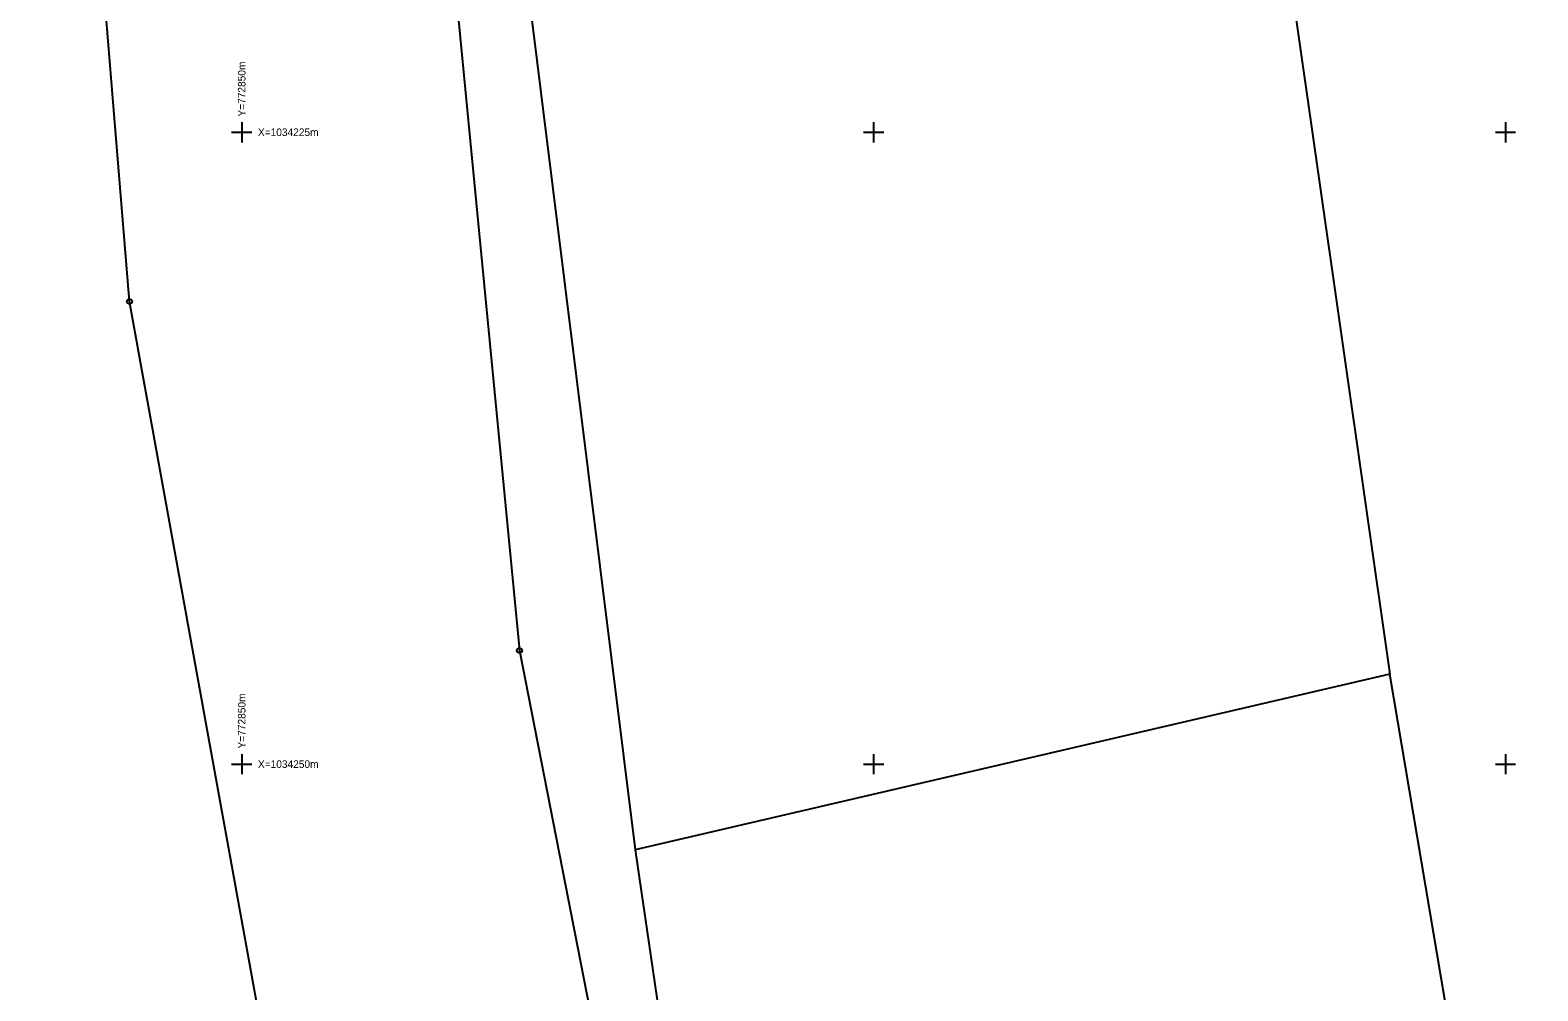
# Model space of a CAD drawing. Extents: x -772865 to -772533, y -1034366 to -1034132.
# Drawn here: x -772858.4 to -772798.7, y -1034259 to -1034221 of the extents above; entities that cross this region are included whole.
import ezdxf

# ---------------------------------------------------------------- set-up
doc = ezdxf.new("R2010")
doc.units = 0
for name, color, linetype in [('KM_hranice', 7, 'Continuous'), ('KM_mezni_znaky', 7, 'Continuous'), ('souradnicova_sit', 7, 'Continuous')]:
    doc.layers.add(name, color=color, linetype=linetype)

msp = doc.modelspace()

# ---------------------------------------------------------------- linework, layer by layer
at = {"layer": 'KM_hranice'}
for p, q in [((-772854.44, -1034231.7), (-772858.37, -1034183.47)), ((-772843.52, -1034198.83), (-772839.01, -1034245.51)), ((-772840, -1034208.77), (-772834.43, -1034253.39)), ((-772809.91, -1034209.22), (-772804.57, -1034246.44)), ((-772847.32, -1034270.94), (-772854.44, -1034231.7)), ((-772839.01, -1034245.51), (-772830.43, -1034289.37)), ((-772804.57, -1034246.44), (-772834.43, -1034253.39)), ((-772798.72, -1034281.08), (-772804.57, -1034246.44)), ((-772834.43, -1034253.39), (-772829.03, -1034290.24))]:
    msp.add_line(p, q, dxfattribs=at)
at = {"layer": 'KM_mezni_znaky'}
for p, q in [((-772854.464, -1034231.7), (-772854.416, -1034231.7)), ((-772839.034, -1034245.51), (-772838.986, -1034245.51))]:
    msp.add_line(p, q, dxfattribs=at)
for points in [[(-772854.41, -1034231.604), (-772854.36, -1034231.64), (-772854.34, -1034231.698), (-772854.36, -1034231.756), (-772854.41, -1034231.792), (-772854.472, -1034231.792), (-772854.522, -1034231.756), (-772854.542, -1034231.698), (-772854.522, -1034231.64), (-772854.472, -1034231.604)], [(-772838.98, -1034245.414), (-772838.93, -1034245.45), (-772838.91, -1034245.508), (-772838.93, -1034245.566), (-772838.98, -1034245.602), (-772839.042, -1034245.602), (-772839.092, -1034245.566), (-772839.112, -1034245.508), (-772839.092, -1034245.45), (-772839.042, -1034245.414)]]:
    msp.add_lwpolyline(points, close=True, dxfattribs=at)
at = {"layer": 'souradnicova_sit'}
for p, q in [((-772850, -1034224.6), (-772850, -1034225.4)), ((-772825, -1034224.6), (-772825, -1034225.4)), ((-772800, -1034224.6), (-772800, -1034225.4)), ((-772850.4, -1034225), (-772849.6, -1034225)), ((-772825.4, -1034225), (-772824.6, -1034225)), ((-772800.4, -1034225), (-772799.6, -1034225)), ((-772850, -1034249.6), (-772850, -1034250.4)), ((-772825, -1034249.6), (-772825, -1034250.4)), ((-772800, -1034249.6), (-772800, -1034250.4)), ((-772850.4, -1034250), (-772849.6, -1034250)), ((-772825.4, -1034250), (-772824.6, -1034250)), ((-772800.4, -1034250), (-772799.6, -1034250))]:
    msp.add_line(p, q, dxfattribs=at)

# ---------------------------------------------------------------- texts
for p in [(-772849.85, -1034224.381), (-772849.85, -1034249.381)]:
    msp.add_text('Y=772850m', height=0.3, rotation=90.01167, dxfattribs=at).set_placement(p)
for s, p in [('X=1034225m', (-772849.358, -1034225.15)), ('X=1034250m', (-772849.358, -1034250.15))]:
    msp.add_text(s, height=0.3, dxfattribs=at).set_placement(p)

doc.saveas('drawing.dxf')
